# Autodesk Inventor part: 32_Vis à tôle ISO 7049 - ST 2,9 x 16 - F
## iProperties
Created: 2002-07
Part Number: 32_Vis à tôle ISO 7049 - ST 2,9 x 16 - F
Material: X4 Cr Mo S18
Document SubType Name: Modélisation
Designer: FIEVET
Company: Lycée Joliot Curie
Control State: 0
Master: False
Checked Out: False
Shininess: 100.0
Length Units: 11269
Angle Units: 11279
Time Units: 11290
Mass Units: 11283
Length Display Precision: 3
Angle Display Precision: 2
Compacted: True
Density: 0.0
Volumn: 0.0
Area: 0.0
PropertySet Name: Model Information
Title: Vis ST CLZ
Subject: NF EN ISO 7049
Author: FIEVET
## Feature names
1. Révolution1 [Revolution]
2. Hélicoïde1
3. Extrusion2
4. Réseau circulaire1 [Circular Pattern]
